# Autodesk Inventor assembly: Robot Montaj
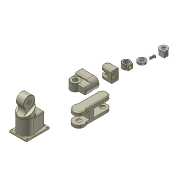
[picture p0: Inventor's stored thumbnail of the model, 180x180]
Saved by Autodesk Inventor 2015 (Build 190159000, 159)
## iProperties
Created: 2014-10
Part Number: Robot Montaj
Document SubType Name: Assembly
Designer: nkaya
Author: nkaya
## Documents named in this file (10)
- D:\yedek\nkaya\word_doc\guz_lisans_2005\04_mtgp\2014_2015_Inventor\Hafta 04\Assembly Örnek Robot\files\Robot Montaj.iam
- D:\yedek\nkaya\word_doc\guz_lisans_2005\04_mtgp\2014_2015_Inventor\Hafta 04\Assembly Örnek Robot\files\Robot-Base-Model-A.ipt
- D:\yedek\nkaya\word_doc\guz_lisans_2005\04_mtgp\2014_2015_Inventor\Hafta 04\Assembly Örnek Robot\files\Robot-Axis1-2.ipt
- D:\yedek\nkaya\word_doc\guz_lisans_2005\04_mtgp\2014_2015_Inventor\Hafta 04\Assembly Örnek Robot\files\Robot-Axis2-3.ipt
- D:\yedek\nkaya\word_doc\guz_lisans_2005\04_mtgp\2014_2015_Inventor\Hafta 04\Assembly Örnek Robot\files\Robot-Axis3-4.ipt
- D:\yedek\nkaya\word_doc\guz_lisans_2005\04_mtgp\2014_2015_Inventor\Hafta 04\Assembly Örnek Robot\files\Robot-Axis4-5.ipt
- D:\yedek\nkaya\word_doc\guz_lisans_2005\04_mtgp\2014_2015_Inventor\Hafta 04\Assembly Örnek Robot\files\Robot-Axis5.ipt
- D:\yedek\nkaya\word_doc\guz_lisans_2005\04_mtgp\2014_2015_Inventor\Hafta 04\Assembly Örnek Robot\files\Robot-Axis5-Adapter.ipt
- D:\yedek\nkaya\word_doc\guz_lisans_2005\04_mtgp\2014_2015_Inventor\Hafta 04\Assembly Örnek Robot\files\Robot-Clamp.ipt
- D:\yedek\nkaya\word_doc\guz_lisans_2005\04_mtgp\2014_2015_Inventor\Hafta 04\Assembly Örnek Robot\files\Robot-Clamp-Mount.ipt
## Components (9 placed, 9 different names)
1. Robot-Base-Model-A:1 — Mate:1, Mate:2
2. Robot-Axis1-2:1 — Mate:1, Mate:2
3. Robot-Axis2-3:1
4. Robot-Axis3-4:1
5. Robot-Axis4-5:1
6. Robot-Axis5:1
7. Robot-Axis5-Adapter:1
8. Robot-Clamp:1
9. Robot-Clamp-Mount:1
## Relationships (2: Mate 2)
- Mate:1: Robot-Base-Model-A:1 ↔ Robot-Axis1-2:1
- Mate:2: Robot-Base-Model-A:1 ↔ Robot-Axis1-2:1
